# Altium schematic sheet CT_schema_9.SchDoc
size 388 x 385 mm
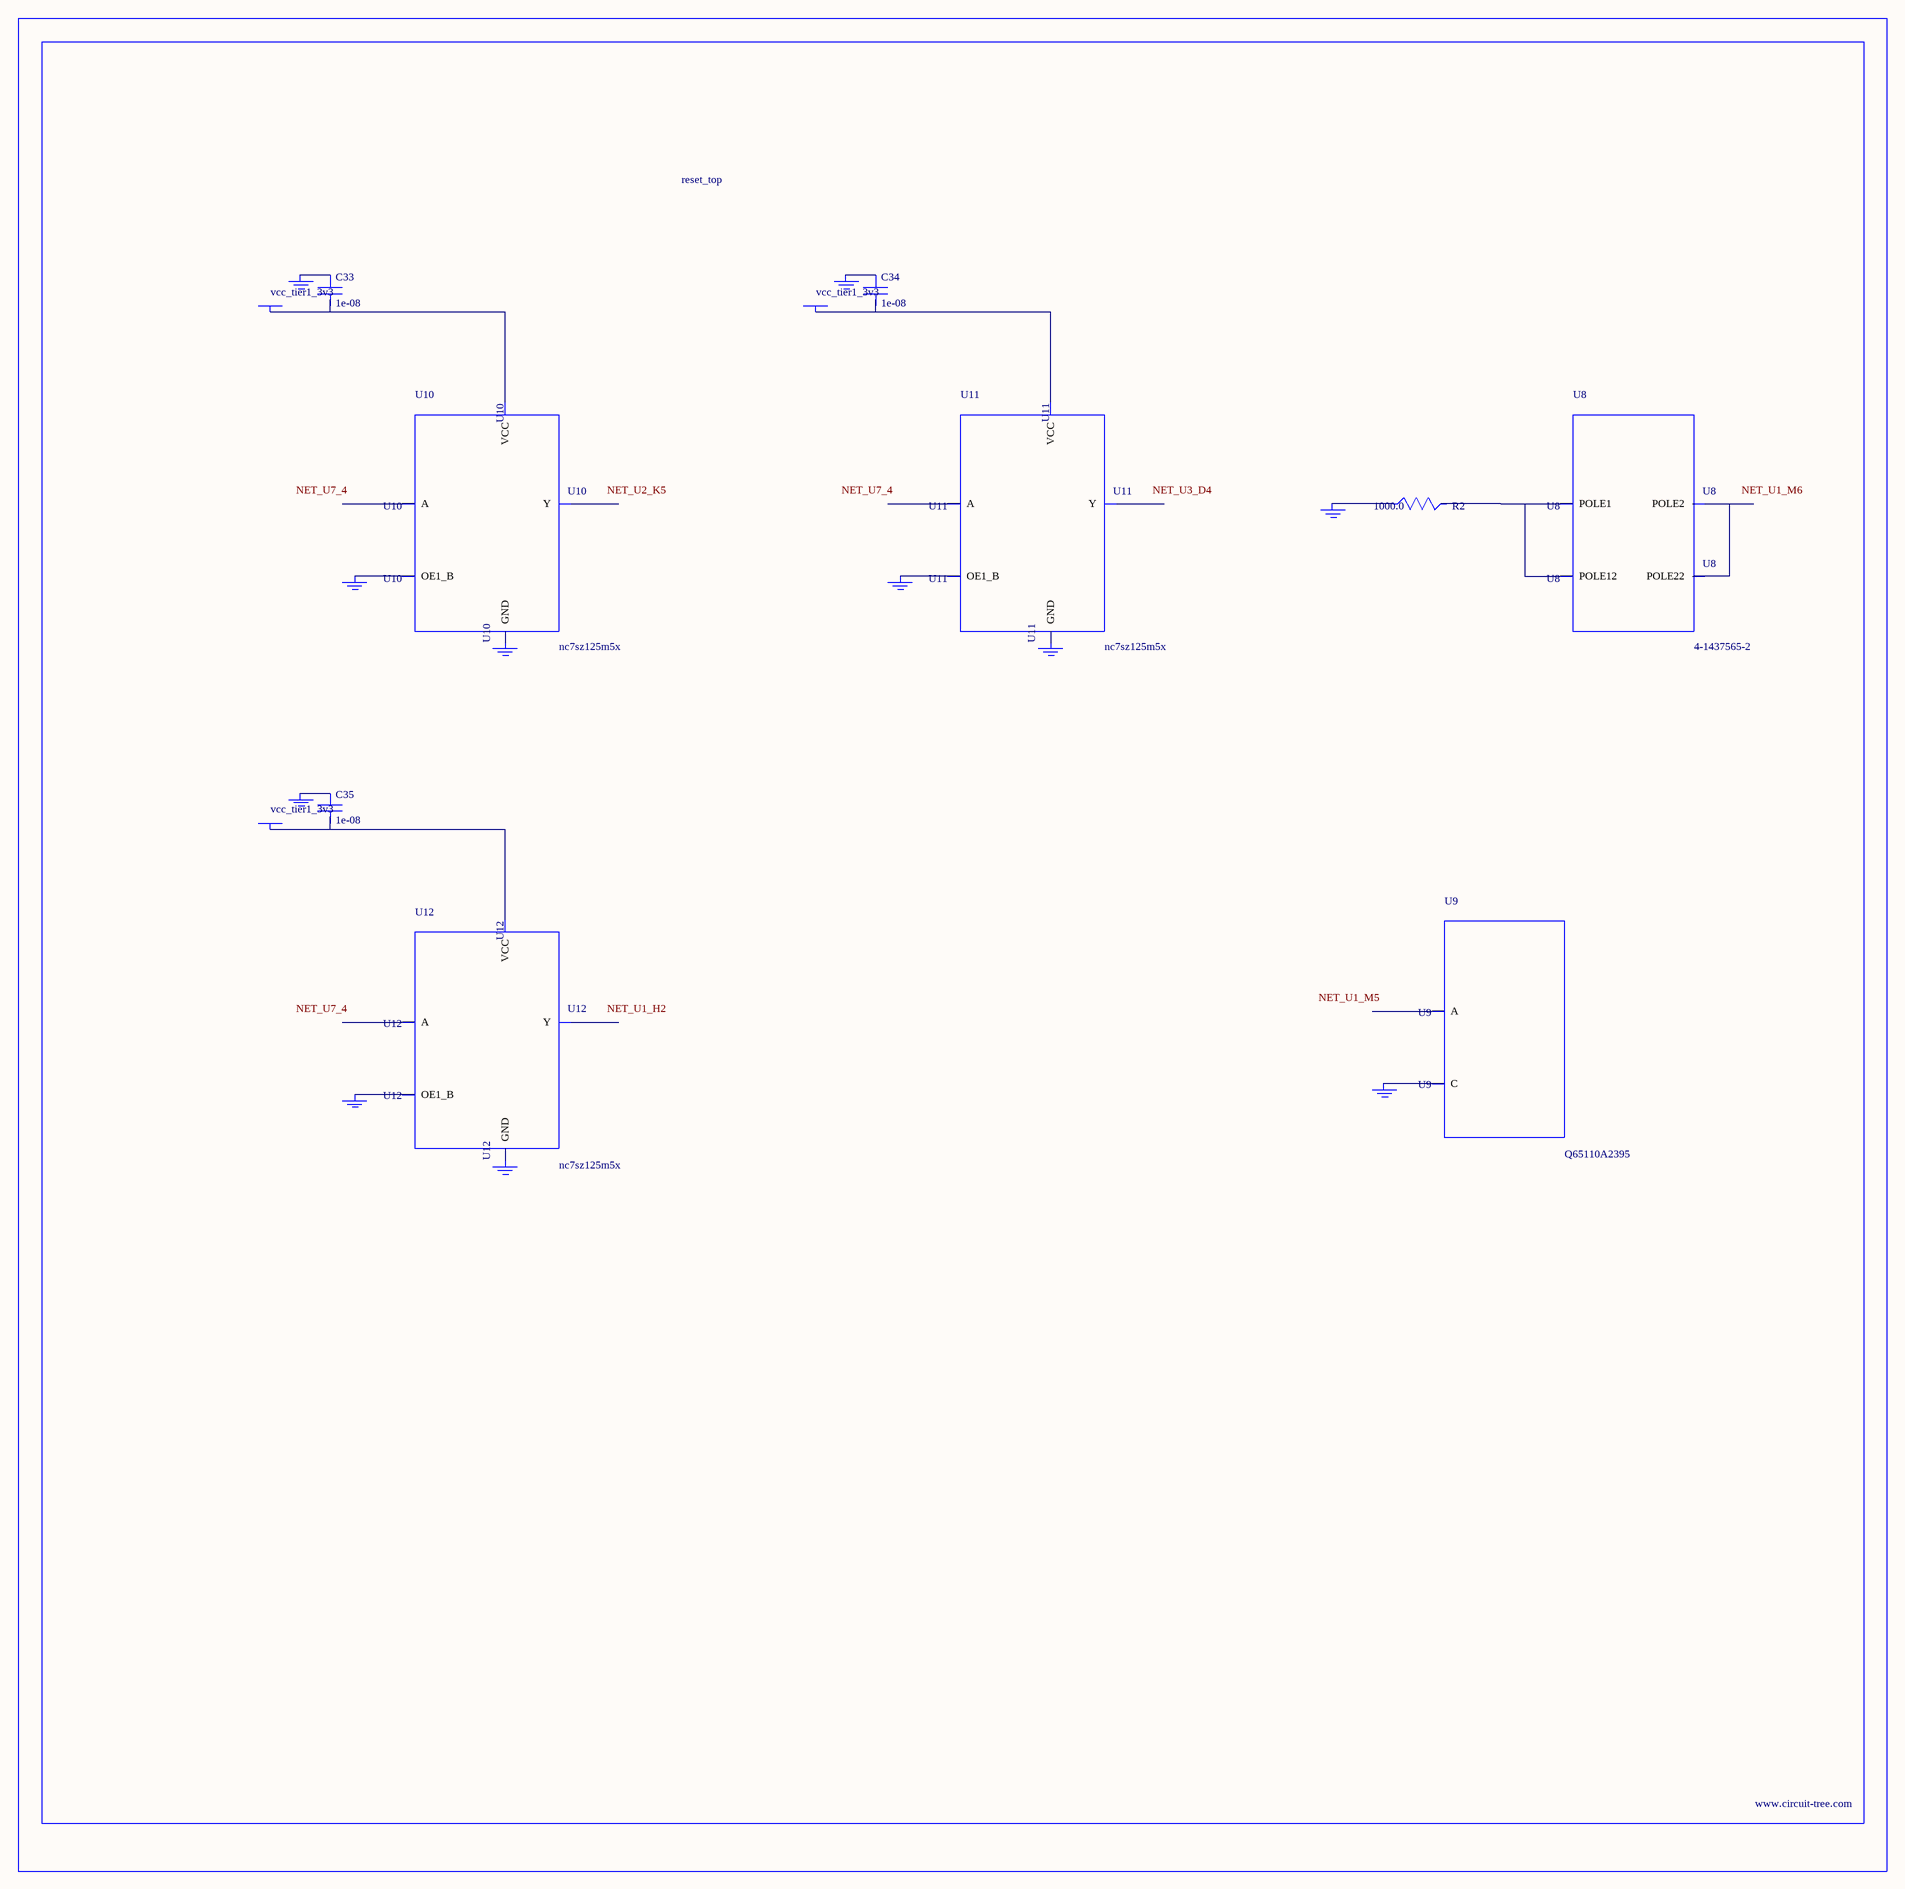
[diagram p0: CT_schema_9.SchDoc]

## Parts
BORDER8  (no value)
C33  1e-08  [C0402]
C34  1e-08  [C0402]
C35  1e-08  [C0402]
GND_INSTANCE_8_0  (no value)
GND_INSTANCE_8_1  (no value)
GND_INSTANCE_8_2  (no value)
GND_INSTANCE_8_3  (no value)
GND_INSTANCE_8_4  (no value)
GND_INSTANCE_8_5  (no value)
GND_INSTANCE_8_6  (no value)
GND_INSTANCE_8_7  (no value)
GND_INSTANCE_8_8  (no value)
GND_INSTANCE_8_9  (no value)
GND_INSTANCE_8_10  (no value)
POWER_INSTANCE_8_0  vcc_tier1_3v3
POWER_INSTANCE_8_1  vcc_tier1_3v3
POWER_INSTANCE_8_2  vcc_tier1_3v3
R2  1000.0  [R0603]
U8  4-1437565-2  [SW_4-1437565-2]
U9  Q65110A2395  [LGM67K-G1J2-24-Z]
U10  nc7sz125m5x  [NC7SZ125M5X]
U11  nc7sz125m5x  [NC7SZ125M5X]
U12  nc7sz125m5x  [NC7SZ125M5X]

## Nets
NetC33_1: C33.1 GND_INSTANCE_8_2.0(GND)
NetC33_2: C33.2 POWER_INSTANCE_8_0.0(PWR) U10.5(VCC)
NetC34_1: C34.1 GND_INSTANCE_8_5.0(GND)
NetC34_2: C34.2 POWER_INSTANCE_8_1.0(PWR) U11.5(VCC)
NetC35_1: C35.1 GND_INSTANCE_8_8.0(GND)
NetC35_2: C35.2 POWER_INSTANCE_8_2.0(PWR) U12.5(VCC)
NetGND_INSTANCE_8_0_0: GND_INSTANCE_8_0.0(GND) R2.1
NetGND_INSTANCE_8_1_0: GND_INSTANCE_8_1.0(GND) U9.C
NetGND_INSTANCE_8_3_0: GND_INSTANCE_8_3.0(GND) U10.1(OE1_B)
NetGND_INSTANCE_8_4_0: GND_INSTANCE_8_4.0(GND) U10.3(GND)
NetGND_INSTANCE_8_6_0: GND_INSTANCE_8_6.0(GND) U11.1(OE1_B)
NetGND_INSTANCE_8_7_0: GND_INSTANCE_8_7.0(GND) U11.3(GND)
NetGND_INSTANCE_8_9_0: GND_INSTANCE_8_9.0(GND) U12.1(OE1_B)
NetGND_INSTANCE_8_10_0: GND_INSTANCE_8_10.0(GND) U12.3(GND)
NetR2_2: R2.2 U8.1(POLE1) U8.2(POLE12)
NetU8_3: U8.3(POLE2) U8.4(POLE22)

Not connected (* = marked no-connect by the designer): U9 A; U10 2(A) 4(Y); U11 2(A) 4(Y); U12 2(A) 4(Y)

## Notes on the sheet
- Labels drawn without touching a wire or pin: NET_U1_H2, NET_U1_M5, NET_U1_M6, NET_U2_K5, NET_U3_D4, NET_U7_4

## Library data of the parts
BORDER8 = BORDER_PAGE8
C33-C35 = C0402C103K3RAC
GND_INSTANCE_8_0-GND_INSTANCE_8_10 = GND
POWER_INSTANCE_8_0-POWER_INSTANCE_8_2 = PWR
R2 = RC0603JR-071KL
